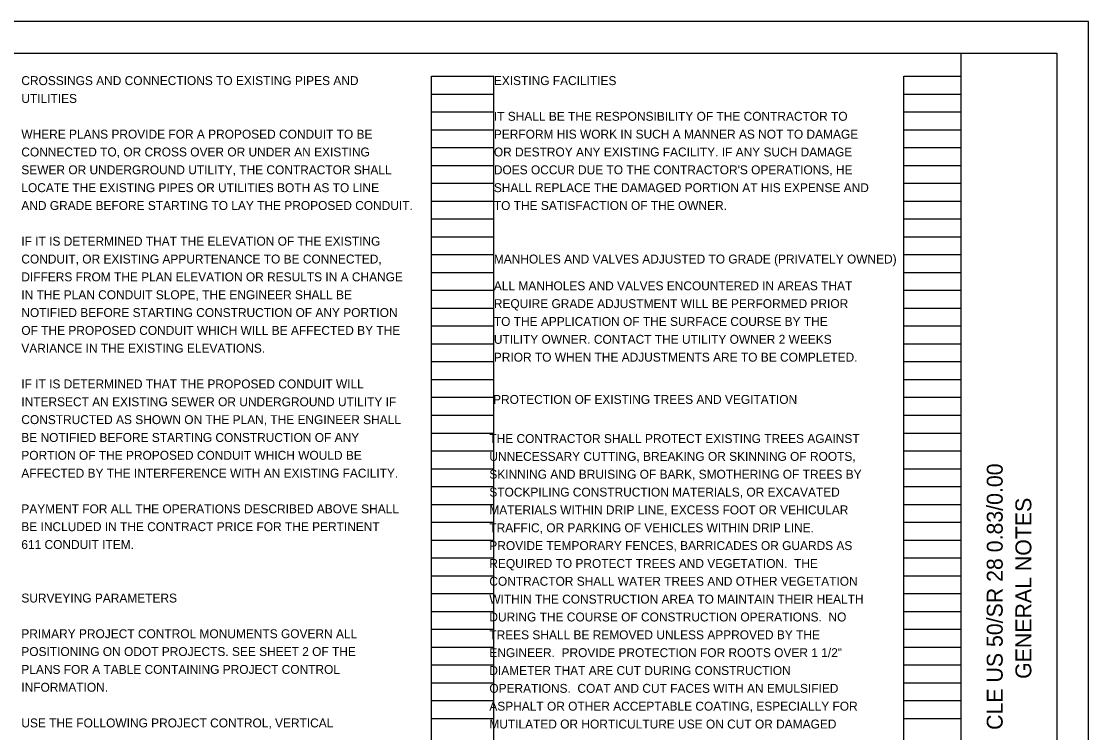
# Model space of a CAD drawing. Extents: x -7.5 to 43.2, y 0 to 22.
# Drawn here: x 17.24 to 34, y 10.84 to 22 of the extents above; entities that cross this region are included whole.
import ezdxf

# ---------------------------------------------------------------- set-up
doc = ezdxf.new("R2010")
doc.units = 0
for name, color, linetype in [('SH_Border', 7, 'Continuous'), ('SH_Cut_Line', 7, 'Continuous'), ('SH_Data', 7, 'Continuous'), ('SH_Text', 7, 'Continuous')]:
    doc.layers.add(name, color=color, linetype=linetype)

msp = doc.modelspace()

# ---------------------------------------------------------------- linework, layer by layer
at = {"layer": 'SH_Border'}
msp.add_line((32, 0.5), (32, 21.5), dxfattribs=at)
msp.add_lwpolyline([(1.5, 21.5), (33.5, 21.5), (33.5, 0.5), (1.5, 0.5)], close=True, dxfattribs=at)
at = {"layer": 'SH_Cut_Line'}
msp.add_lwpolyline([(0, 0), (34, 0), (34, 22), (0, 22)], close=True, dxfattribs=at)
at = {"layer": 'SH_Data'}
for p, q in [((23.68, 0.98), (23.68, 21.14)), ((23.68, 21.14), (24.66, 21.14)), ((24.66, 0.98), (24.66, 21.14)), ((31.1, 0.98), (31.1, 21.14)), ((31.1, 21.14), (32, 21.14)), ((32, 0.98), (32, 21.14)), ((23.68, 20.86), (24.66, 20.86)), ((31.1, 20.86), (32, 20.86)), ((23.68, 20.58), (24.66, 20.58)), ((31.1, 20.58), (32, 20.58)), ((23.68, 20.3), (24.66, 20.3)), ((31.1, 20.3), (32, 20.3)), ((23.68, 20.02), (24.66, 20.02)), ((31.1, 20.02), (32, 20.02)), ((23.68, 19.74), (24.66, 19.74)), ((31.1, 19.74), (32, 19.74)), ((23.68, 19.46), (24.66, 19.46)), ((31.1, 19.46), (32, 19.46)), ((23.68, 19.18), (24.66, 19.18)), ((31.1, 19.18), (32, 19.18)), ((23.68, 18.9), (24.66, 18.9)), ((31.1, 18.9), (32, 18.9)), ((23.68, 18.62), (24.66, 18.62)), ((31.1, 18.62), (32, 18.62)), ((23.68, 18.34), (24.66, 18.34)), ((31.1, 18.34), (32, 18.34)), ((23.68, 18.06), (24.66, 18.06)), ((31.1, 18.06), (32, 18.06)), ((23.68, 17.78), (24.66, 17.78)), ((31.1, 17.78), (32, 17.78)), ((23.68, 17.5), (24.66, 17.5)), ((31.1, 17.5), (32, 17.5)), ((23.68, 17.22), (24.66, 17.22)), ((31.1, 17.22), (32, 17.22)), ((23.68, 16.94), (24.66, 16.94)), ((31.1, 16.94), (32, 16.94)), ((23.68, 16.66), (24.66, 16.66)), ((31.1, 16.66), (32, 16.66)), ((23.68, 16.38), (24.66, 16.38)), ((31.1, 16.38), (32, 16.38)), ((23.68, 16.1), (24.66, 16.1)), ((31.1, 16.1), (32, 16.1)), ((23.68, 15.82), (24.66, 15.82)), ((31.1, 15.82), (32, 15.82)), ((23.68, 15.54), (24.66, 15.54)), ((31.1, 15.54), (32, 15.54)), ((23.68, 15.26), (24.66, 15.26)), ((31.1, 15.26), (32, 15.26)), ((23.68, 14.98), (24.66, 14.98)), ((31.1, 14.98), (32, 14.98)), ((23.68, 14.7), (24.66, 14.7)), ((31.1, 14.7), (32, 14.7)), ((23.68, 14.42), (24.66, 14.42)), ((31.1, 14.42), (32, 14.42)), ((23.68, 14.14), (24.66, 14.14)), ((31.1, 14.14), (32, 14.14)), ((23.68, 13.86), (24.66, 13.86)), ((31.1, 13.86), (32, 13.86)), ((23.68, 13.58), (24.66, 13.58)), ((31.1, 13.58), (32, 13.58)), ((23.68, 13.3), (24.66, 13.3)), ((31.1, 13.3), (32, 13.3)), ((23.68, 13.02), (24.66, 13.02)), ((31.1, 13.02), (32, 13.02)), ((23.68, 12.74), (24.66, 12.74)), ((31.1, 12.74), (32, 12.74)), ((23.68, 12.46), (24.66, 12.46)), ((31.1, 12.46), (32, 12.46)), ((23.68, 12.18), (24.66, 12.18)), ((31.1, 12.18), (32, 12.18)), ((23.68, 11.9), (24.66, 11.9)), ((31.1, 11.9), (32, 11.9)), ((23.68, 11.62), (24.66, 11.62)), ((31.1, 11.62), (32, 11.62)), ((23.68, 11.34), (24.66, 11.34)), ((31.1, 11.34), (32, 11.34)), ((23.68, 11.06), (24.66, 11.06)), ((31.1, 11.06), (32, 11.06))]:
    msp.add_line(p, q, dxfattribs=at)

# ---------------------------------------------------------------- texts
for s, p in [('CLE US 50/SR 28 0.83/0.00', (32.65, 10.881)), ('GENERAL NOTES', (33.1, 11.682))]:
    msp.add_text(s, height=0.25, rotation=90, dxfattribs=at).set_placement(p)
at = {"layer": 'SH_Text'}
for s, p in [('CROSSINGS AND CONNECTIONS TO EXISTING PIPES AND', (17.24, 21)), ('EXISTING FACILITIES', (24.66, 21)), ('UTILITIES', (17.24, 20.72)), ('IT SHALL BE THE RESPONSIBILITY OF THE CONTRACTOR TO', (24.66, 20.44)), ('WHERE PLANS PROVIDE FOR A PROPOSED CONDUIT TO BE', (17.24, 20.16)), ('PERFORM HIS WORK IN SUCH A MANNER AS NOT TO DAMAGE', (24.66, 20.16)), ('CONNECTED TO, OR CROSS OVER OR UNDER AN EXISTING', (17.24, 19.88)), ('OR DESTROY ANY EXISTING FACILITY. IF ANY SUCH DAMAGE', (24.66, 19.88)), ('SEWER OR UNDERGROUND UTILITY, THE CONTRACTOR SHALL', (17.24, 19.6)), ("DOES OCCUR DUE TO THE CONTRACTOR'S OPERATIONS, HE", (24.66, 19.6)), ('LOCATE THE EXISTING PIPES OR UTILITIES BOTH AS TO LINE', (17.24, 19.32)), ('SHALL REPLACE THE DAMAGED PORTION AT HIS EXPENSE AND', (24.66, 19.32)), ('AND GRADE BEFORE STARTING TO LAY THE PROPOSED CONDUIT.', (17.24, 19.04)), ('TO THE SATISFACTION OF THE OWNER.', (24.66, 19.04)), ('IF IT IS DETERMINED THAT THE ELEVATION OF THE EXISTING', (17.24, 18.48)), ('CONDUIT, OR EXISTING APPURTENANCE TO BE CONNECTED,', (17.24, 18.2)), ('MANHOLES AND VALVES ADJUSTED TO GRADE (PRIVATELY OWNED)', (24.66, 18.2)), ('DIFFERS FROM THE PLAN ELEVATION OR RESULTS IN A CHANGE', (17.24, 17.92)), ('IN THE PLAN CONDUIT SLOPE, THE ENGINEER SHALL BE', (17.24, 17.64)), ('ALL MANHOLES AND VALVES ENCOUNTERED IN AREAS THAT ', (24.66, 17.78)), ('REQUIRE GRADE ADJUSTMENT WILL BE PERFORMED PRIOR ', (24.66, 17.5)), ('NOTIFIED BEFORE STARTING CONSTRUCTION OF ANY PORTION', (17.24, 17.36)), ('TO THE APPLICATION OF THE SURFACE COURSE BY THE ', (24.66, 17.22)), ('OF THE PROPOSED CONDUIT WHICH WILL BE AFFECTED BY THE', (17.24, 17.08)), ('VARIANCE IN THE EXISTING ELEVATIONS.', (17.24, 16.8)), ('UTILITY OWNER. CONTACT THE UTILITY OWNER 2 WEEKS ', (24.66, 16.94)), ('PRIOR TO WHEN THE ADJUSTMENTS ARE TO BE COMPLETED.', (24.66, 16.66)), ('IF IT IS DETERMINED THAT THE PROPOSED CONDUIT WILL', (17.24, 16.24)), ('INTERSECT AN EXISTING SEWER OR UNDERGROUND UTILITY IF', (17.24, 15.96)), ('PROTECTION OF EXISTING TREES AND VEGITATION', (24.648, 15.997)), ('CONSTRUCTED AS SHOWN ON THE PLAN, THE ENGINEER SHALL', (17.24, 15.68)), ('BE NOTIFIED BEFORE STARTING CONSTRUCTION OF ANY', (17.24, 15.4)), ('THE CONTRACTOR SHALL PROTECT EXISTING TREES AGAINST ', (24.589, 15.383)), ('PORTION OF THE PROPOSED CONDUIT WHICH WOULD BE', (17.24, 15.12)), ('UNNECESSARY CUTTING, BREAKING OR SKINNING OF ROOTS, ', (24.589, 15.103)), ('AFFECTED BY THE INTERFERENCE WITH AN EXISTING FACILITY.', (17.24, 14.84)), ('SKINNING AND BRUISING OF BARK, SMOTHERING OF TREES BY ', (24.589, 14.823)), ('STOCKPILING CONSTRUCTION MATERIALS, OR EXCAVATED ', (24.589, 14.543)), ('PAYMENT FOR ALL THE OPERATIONS DESCRIBED ABOVE SHALL', (17.24, 14.28)), ('MATERIALS WITHIN DRIP LINE, EXCESS FOOT OR VEHICULAR ', (24.589, 14.263)), ('BE INCLUDED IN THE CONTRACT PRICE FOR THE PERTINENT', (17.24, 14)), ('TRAFFIC, OR PARKING OF VEHICLES WITHIN DRIP LINE.  ', (24.589, 13.983)), ('611 CONDUIT ITEM.', (17.24, 13.72)), ('PROVIDE TEMPORARY FENCES, BARRICADES OR GUARDS AS ', (24.589, 13.703)), ('REQUIRED TO PROTECT TREES AND VEGETATION.  THE ', (24.589, 13.423)), ('CONTRACTOR SHALL WATER TREES AND OTHER VEGETATION ', (24.589, 13.143)), ('SURVEYING PARAMETERS', (17.24, 12.88)), ('WITHIN THE CONSTRUCTION AREA TO MAINTAIN THEIR HEALTH ', (24.589, 12.863)), ('DURING THE COURSE OF CONSTRUCTION OPERATIONS.  NO ', (24.589, 12.583)), ('PRIMARY PROJECT CONTROL MONUMENTS GOVERN ALL', (17.24, 12.32)), ('TREES SHALL BE REMOVED UNLESS APPROVED BY THE ', (24.589, 12.303)), ('POSITIONING ON ODOT PROJECTS. SEE SHEET 2 OF THE', (17.24, 12.04)), ('ENGINEER.  PROVIDE PROTECTION FOR ROOTS OVER 1 1/2" ', (24.589, 12.023)), ('PLANS FOR A TABLE CONTAINING PROJECT CONTROL', (17.24, 11.76)), ('DIAMETER THAT ARE CUT DURING CONSTRUCTION ', (24.589, 11.743)), ('INFORMATION.', (17.24, 11.48)), ('OPERATIONS.  COAT AND CUT FACES WITH AN EMULSIFIED ', (24.589, 11.463)), ('ASPHALT OR OTHER ACCEPTABLE COATING, ESPECIALLY FOR ', (24.589, 11.183)), ('USE THE FOLLOWING PROJECT CONTROL, VERTICAL', (17.24, 10.92)), ('MUTILATED OR HORTICULTURE USE ON CUT OR DAMAGED ', (24.589, 10.903))]:
    msp.add_text(s, height=0.14, dxfattribs=at).set_placement(p)

doc.saveas('drawing.dxf')
